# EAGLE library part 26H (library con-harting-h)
CONNECTOR
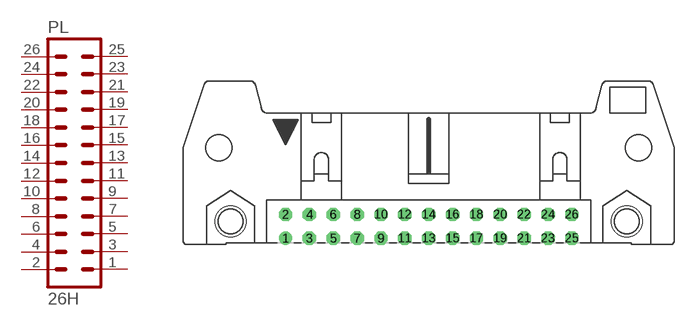
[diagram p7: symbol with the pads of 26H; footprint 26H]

Designator prefix PL

## 26H (OC_FARNELL: unknown; OC_NEWARK: unknown)  [26H]
1  1  pas
2  2  pas
3  3  pas
4  4  pas
5  5  pas
6  6  pas
7  7  pas
8  8  pas
9  9  pas
10  10  pas
11  11  pas
12  12  pas
13  13  pas
14  14  pas
15  15  pas
16  16  pas
17  17  pas
18  18  pas
19  19  pas
20  20  pas
21  21  pas
22  22  pas
23  23  pas
24  24  pas
25  25  pas
26  26  pas

## Footprint 26H (pad centres in mm)
CONNECTOR
drill 0.914 round: 1 -15.24,-1.27
drill 0.914 octagon: 2 -15.24,1.27; 3 -12.7,-1.27; 4 -12.7,1.27; 5 -10.16,-1.27; 6 -10.16,1.27; 7 -7.62,-1.27; 8 -7.62,1.27; 9 -5.08,-1.27; 10 -5.08,1.27; 11 -2.54,-1.27; 12 -2.54,1.27; 13 0,-1.27; 14 0,1.27; 15 2.54,-1.27; 16 2.54,1.27; 17 5.08,-1.27; 18 5.08,1.27; 19 7.62,-1.27; 20 7.62,1.27; 21 10.16,-1.27; 22 10.16,1.27; 23 12.7,-1.27; 24 12.7,1.27; 25 15.24,-1.27; 26 15.24,1.27
hole 3.302 at -21.082,0.533
hole 3.302 at 21.082,0.533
